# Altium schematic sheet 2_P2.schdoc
size 309 x 223 mm; Symbol: Sheet-Symbol_A4; Device: Sheet-Symbol_A4; @Page Name: P2; @Create Date: 2023-03-17; @Page Count: 2; @Page No: 2; @Project Name: flatbox; @Schematic Name: Schematic1; @Update Date: 2023-03-18; Company: 嘉立创EDA; Page Size: A4; Version: V1.0
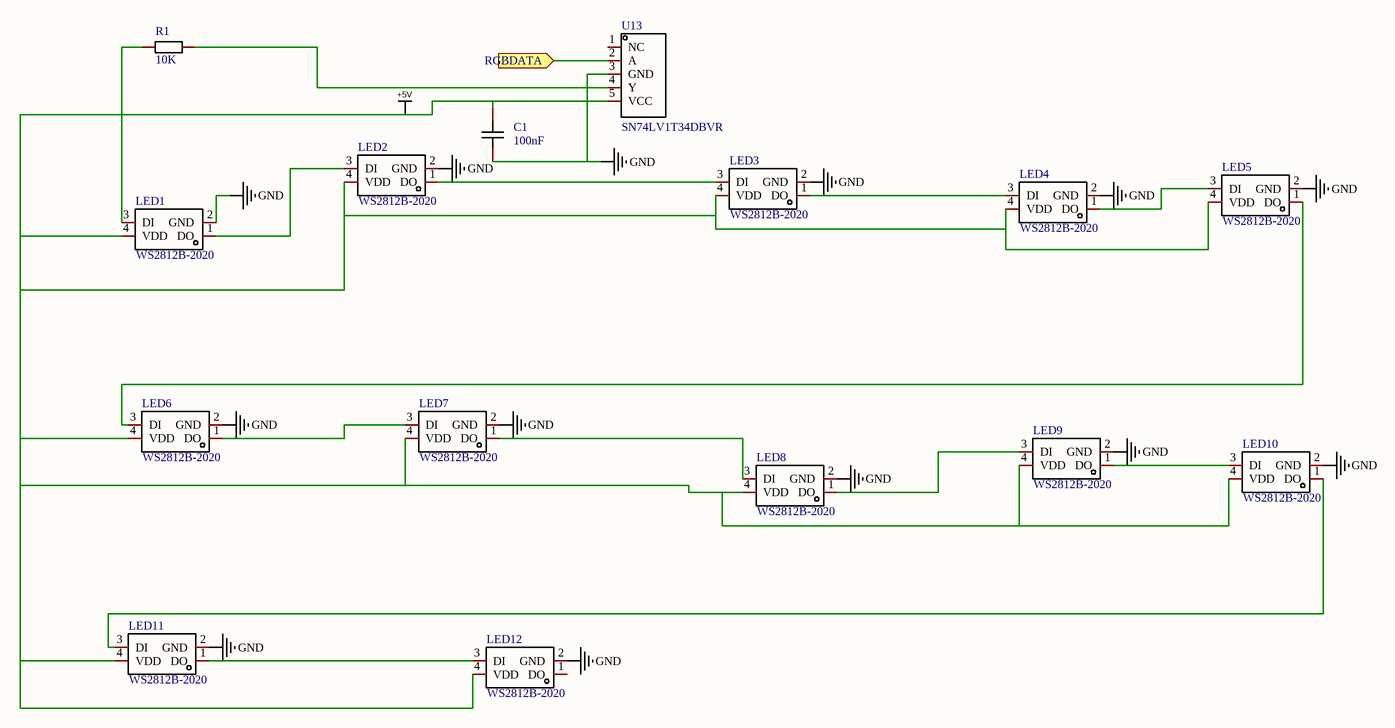
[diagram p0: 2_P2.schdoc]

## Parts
C1  100nF  [C0603]
LED1  WS2812B-2020  [LED-SMD_4P-L2.0-W2.0-TL_WS2812B-2020]
LED2  WS2812B-2020  [LED-SMD_4P-L2.0-W2.0-TL_WS2812B-2020]
LED3  WS2812B-2020  [LED-SMD_4P-L2.0-W2.0-TL_WS2812B-2020]
LED4  WS2812B-2020  [LED-SMD_4P-L2.0-W2.0-TL_WS2812B-2020]
LED5  WS2812B-2020  [LED-SMD_4P-L2.0-W2.0-TL_WS2812B-2020]
LED6  WS2812B-2020  [LED-SMD_4P-L2.0-W2.0-TL_WS2812B-2020]
LED7  WS2812B-2020  [LED-SMD_4P-L2.0-W2.0-TL_WS2812B-2020]
LED8  WS2812B-2020  [LED-SMD_4P-L2.0-W2.0-TL_WS2812B-2020]
LED9  WS2812B-2020  [LED-SMD_4P-L2.0-W2.0-TL_WS2812B-2020]
LED10  WS2812B-2020  [LED-SMD_4P-L2.0-W2.0-TL_WS2812B-2020]
LED11  WS2812B-2020  [LED-SMD_4P-L2.0-W2.0-TL_WS2812B-2020]
LED12  WS2812B-2020  [LED-SMD_4P-L2.0-W2.0-TL_WS2812B-2020]
R1  10K  [R0603]
U13  SN74LV1T34DBVR  [SOT-23-5_L3.0-W1.7-P0.95-LS2.8-BR]

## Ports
RGBDATA (in)

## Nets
+5V: C1.2 LED1.4(VDD) LED2.4(VDD) LED3.4(VDD) LED4.4(VDD) LED5.4(VDD) LED6.4(VDD) LED7.4(VDD) LED8.4(VDD) LED9.4(VDD) LED10.4(VDD) LED11.4(VDD) LED12.4(VDD) U13.5(VCC)
GND: C1.1 LED1.2(GND) LED2.2(GND) LED3.2(GND) LED4.2(GND) LED5.2(GND) LED6.2(GND) LED7.2(GND) LED8.2(GND) LED9.2(GND) LED10.2(GND) LED11.2(GND) LED12.2(GND) U13.3(GND)
RGBDATA: U13.2(A) ; port RGBDATA
NetLED1_1: LED1.1(DO) LED2.3(DI)
NetLED1_3: LED1.3(DI) R1.1
NetLED2_1: LED2.1(DO) LED3.3(DI)
NetLED3_1: LED3.1(DO) LED4.3(DI)
NetLED4_1: LED4.1(DO) LED5.3(DI)
NetLED5_1: LED5.1(DO) LED6.3(DI)
NetLED6_1: LED6.1(DO) LED7.3(DI)
NetLED7_1: LED7.1(DO) LED8.3(DI)
NetLED8_1: LED8.1(DO) LED9.3(DI)
NetLED9_1: LED9.1(DO) LED10.3(DI)
NetLED10_1: LED10.1(DO) LED11.3(DI)
NetLED11_1: LED11.1(DO) LED12.3(DI)
NetR1_2: R1.2 U13.4(Y)

Not connected (* = marked no-connect by the designer): LED12 1(DO); U13 1(NC)

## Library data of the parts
C1 = CAP_0603: Symbol: CapAcitance; Convert to PCB: yes
LED1-LED12 = WS2812B-2020: 发光颜色:RGB三色;二极管配置:-;透镜颜色:-;主波长:470.4nm；622.5nm；515.6nm;峰值波长:-;色温:-;测试电流:12mA;功率:-;发光角度:-;安装方式:-;工作温度:-;; Manufacturer: worldsemi; Add into BOM: yes; Emitted Color: RGB三色; Forward Current: 12mA
R1 = Res_0603: Symbol: 电阻; Convert to PCB: yes
U13 = SN74LV1T34DBVR: 类型:缓冲器，非反相;电源电压:1.6V~5.5V;输入类型:-;输出类型:推挽;低电平输出电流(IOL):8mA;高电平输出电流(IOH):8mA;工作温度:-40℃~+125℃;; Manufacturer: TI(德州仪器); Add into BOM: yes; output type: 推挽; Current-OutputLow: 8mA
